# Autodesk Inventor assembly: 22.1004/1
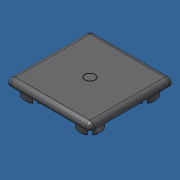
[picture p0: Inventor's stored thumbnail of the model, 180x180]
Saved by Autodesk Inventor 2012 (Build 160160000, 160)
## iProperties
Created: 2011-07
Part Number: 22.1004/1
Document SubType Name: Assembly
Designer: Administrator
Description: END CAP 45X45 GRAY
Vendor: S
Mass: 6.19693 g
Surface Area: 64.7898 cm^2
Volume: 5.84616 cm^3
Density: 1.06 g/cm^3
Author: Administrator
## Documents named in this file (4)
- C:\Andys Backup Data\ANDY'S INVENTOR\INVENTOR LIBRARIES\PARTS LIBRARY\END CAPS\22.1004_1 END CAP 45X45 GRAY.iam
- 22.1004/1 END CAP 45X45 GRAY.iam
- C:\Andys Backup Data\ANDY'S INVENTOR\INVENTOR LIBRARIES\PARTS LIBRARY\END CAPS\SUBCOMPONENTS\22.1004_1 END CAP 45X45 GRAY.ipt
- C:\Andys Backup Data\ANDY'S INVENTOR\INVENTOR LIBRARIES\PARTS LIBRARY\END CAPS\SUBCOMPONENTS\END CAP DOWEL GRAY.ipt
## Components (2 placed, 2 different names)
1. 22.1004_1 END CAP 45X45 GRAY:1 — Mate:1, Flush:1
2. END CAP DOWEL GRAY:1 — Mate:1, Flush:1
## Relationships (2: Mate 1, Flush 1)
- Mate:1: 22.1004_1 END CAP 45X45 GRAY:1 ↔ END CAP DOWEL GRAY:1
- Flush:1: 22.1004_1 END CAP 45X45 GRAY:1 ↔ END CAP DOWEL GRAY:1
